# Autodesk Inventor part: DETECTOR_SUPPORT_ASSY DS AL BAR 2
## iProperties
Shininess: 64.0
Length Units: 11272
Angle Units: 11279
Time Units: 11290
Mass Units: 11286
Length Display Precision: 3
Angle Display Precision: 2
Compacted: True
Part Number: DETECTOR_SUPPORT_ASSY DS AL BAR 2
Document SubType Name: Modeling
Created: 2004-08
Designer: John Blackburn
Material: ALUMINUM
Manufacturer: Standard
Standards Organization: Custom
Density: 0.0
Volumn: 0.0
Area: 0.0
PropertySet Name: Model Information
Control State: 0
Master: False
Checked Out: False
Author: John Blackburn
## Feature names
1. ExtrusionBlind1
2. AM_HOLE_SI0029_1 [Hole]
3. Rectangular Pattern1
